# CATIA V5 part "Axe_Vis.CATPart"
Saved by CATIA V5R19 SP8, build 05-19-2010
Part number: Axe_Vis
Nomenclature: 70_l
Bounding box of the stored display mesh (mm): x -2.5 to 2.5, y -10.85 to 10.85, z -2.5 to 2.5
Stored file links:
  C:\Users\rphgr\Desktop\0_Tapis_TC520B_vitesse\Axe_Vis.CATPart
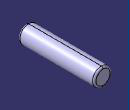
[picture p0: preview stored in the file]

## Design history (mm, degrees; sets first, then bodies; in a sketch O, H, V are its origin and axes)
Body1 (main body)
  AxisSystem1: origin (0, 0, 0), X (1, 0, 0), Y (0, 1, 0), Z (0, 0, 1)
  Sketch1 on ZX plane of AxisSystem1, origin (0, 0, 0), H (0, 0, 1), V (1, 0, 0)
    circle A1 centre (0, 0) radius 2.5
    radius A1 = 2.5
  Pad1: profile Sketch1, direction (0, 1, 0), length 10.85, mirrored extent
  Fillet1: radius 0.5, on end face of Pad1; start face of Pad1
